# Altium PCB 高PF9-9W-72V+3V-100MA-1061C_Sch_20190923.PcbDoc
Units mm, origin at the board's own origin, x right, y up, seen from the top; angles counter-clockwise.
Board outline 296.5 x 139.5 mm, 2 copper layers (Top Layer, Bottom Layer); 45 components, 27 nets, 117 pads, 18 vias.
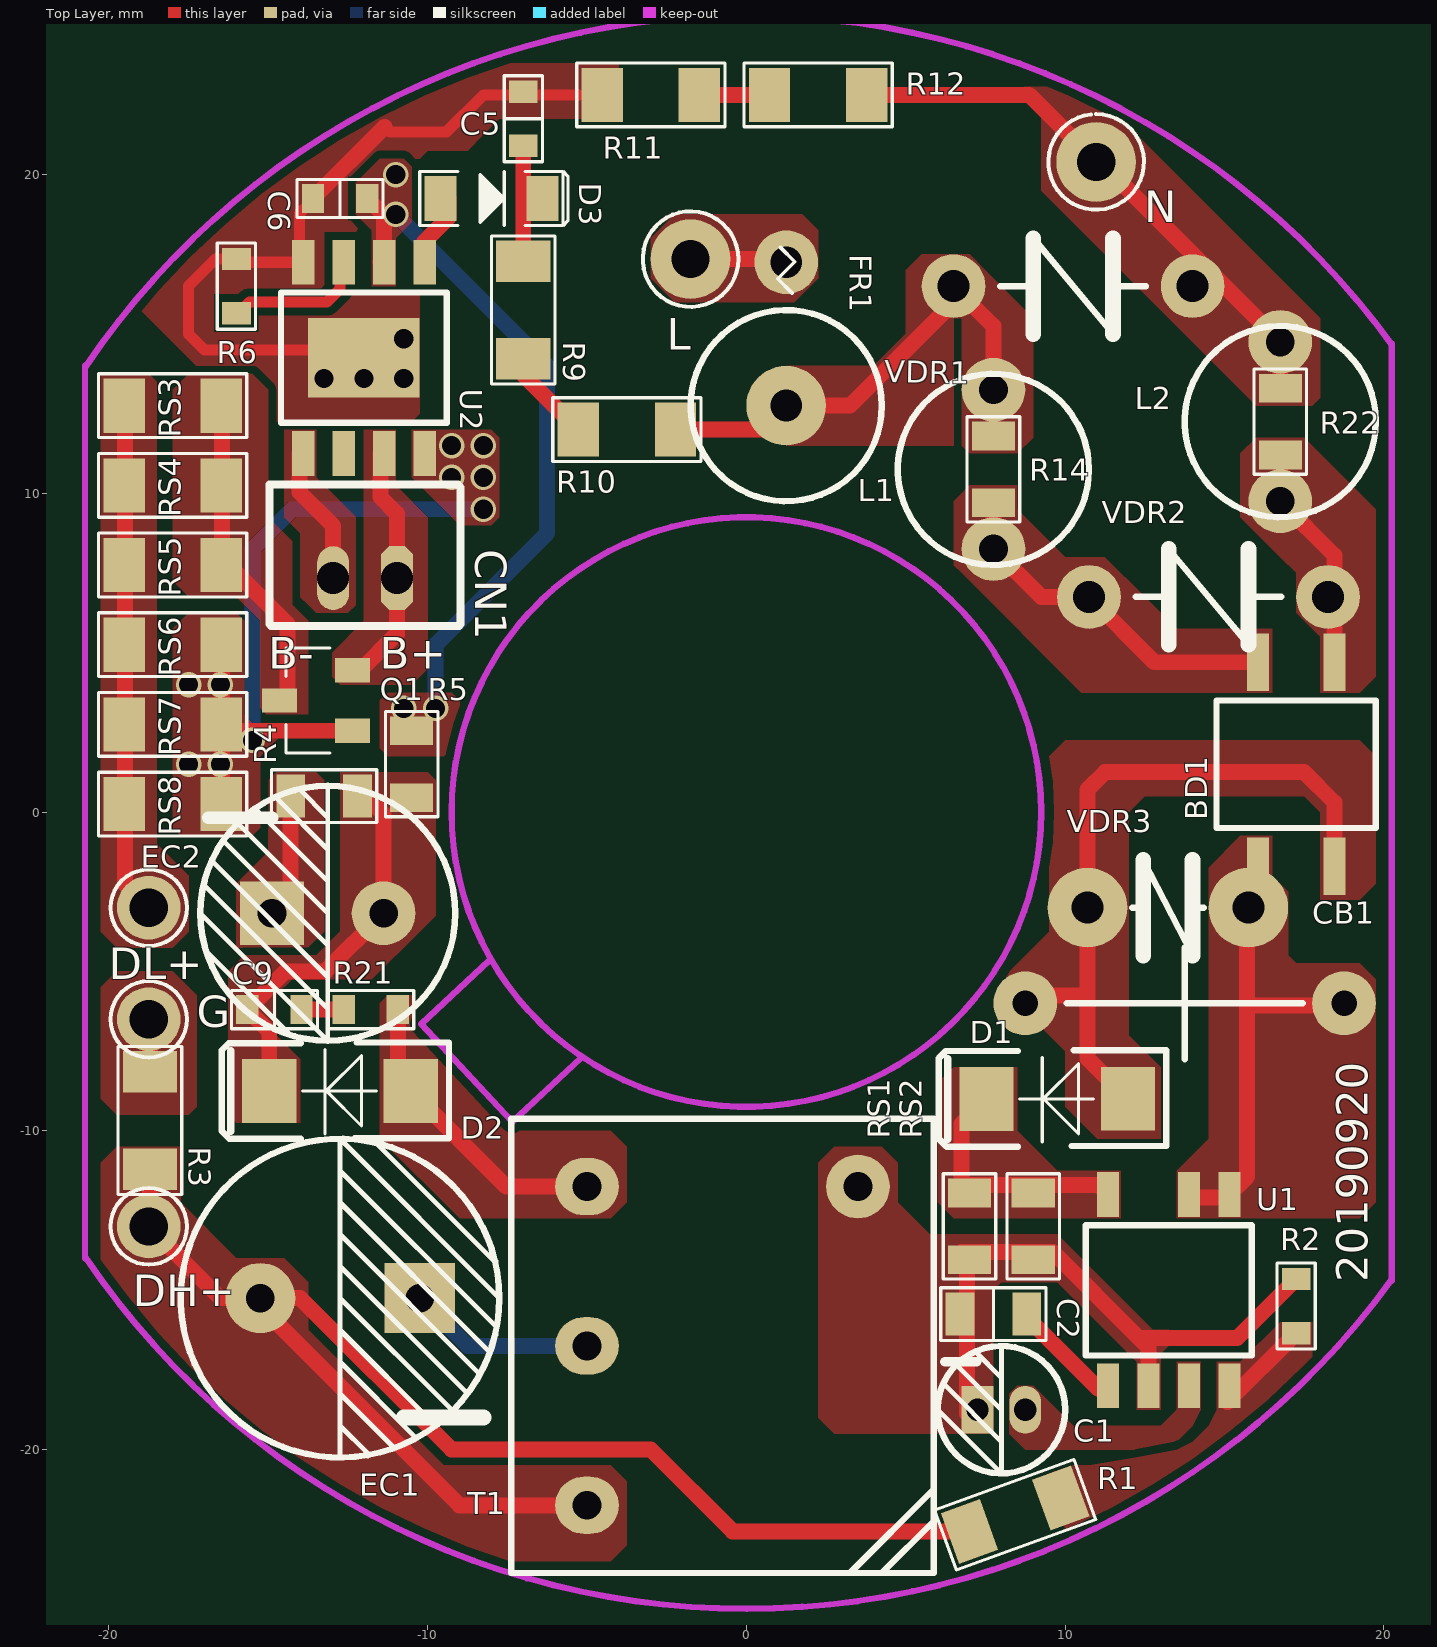
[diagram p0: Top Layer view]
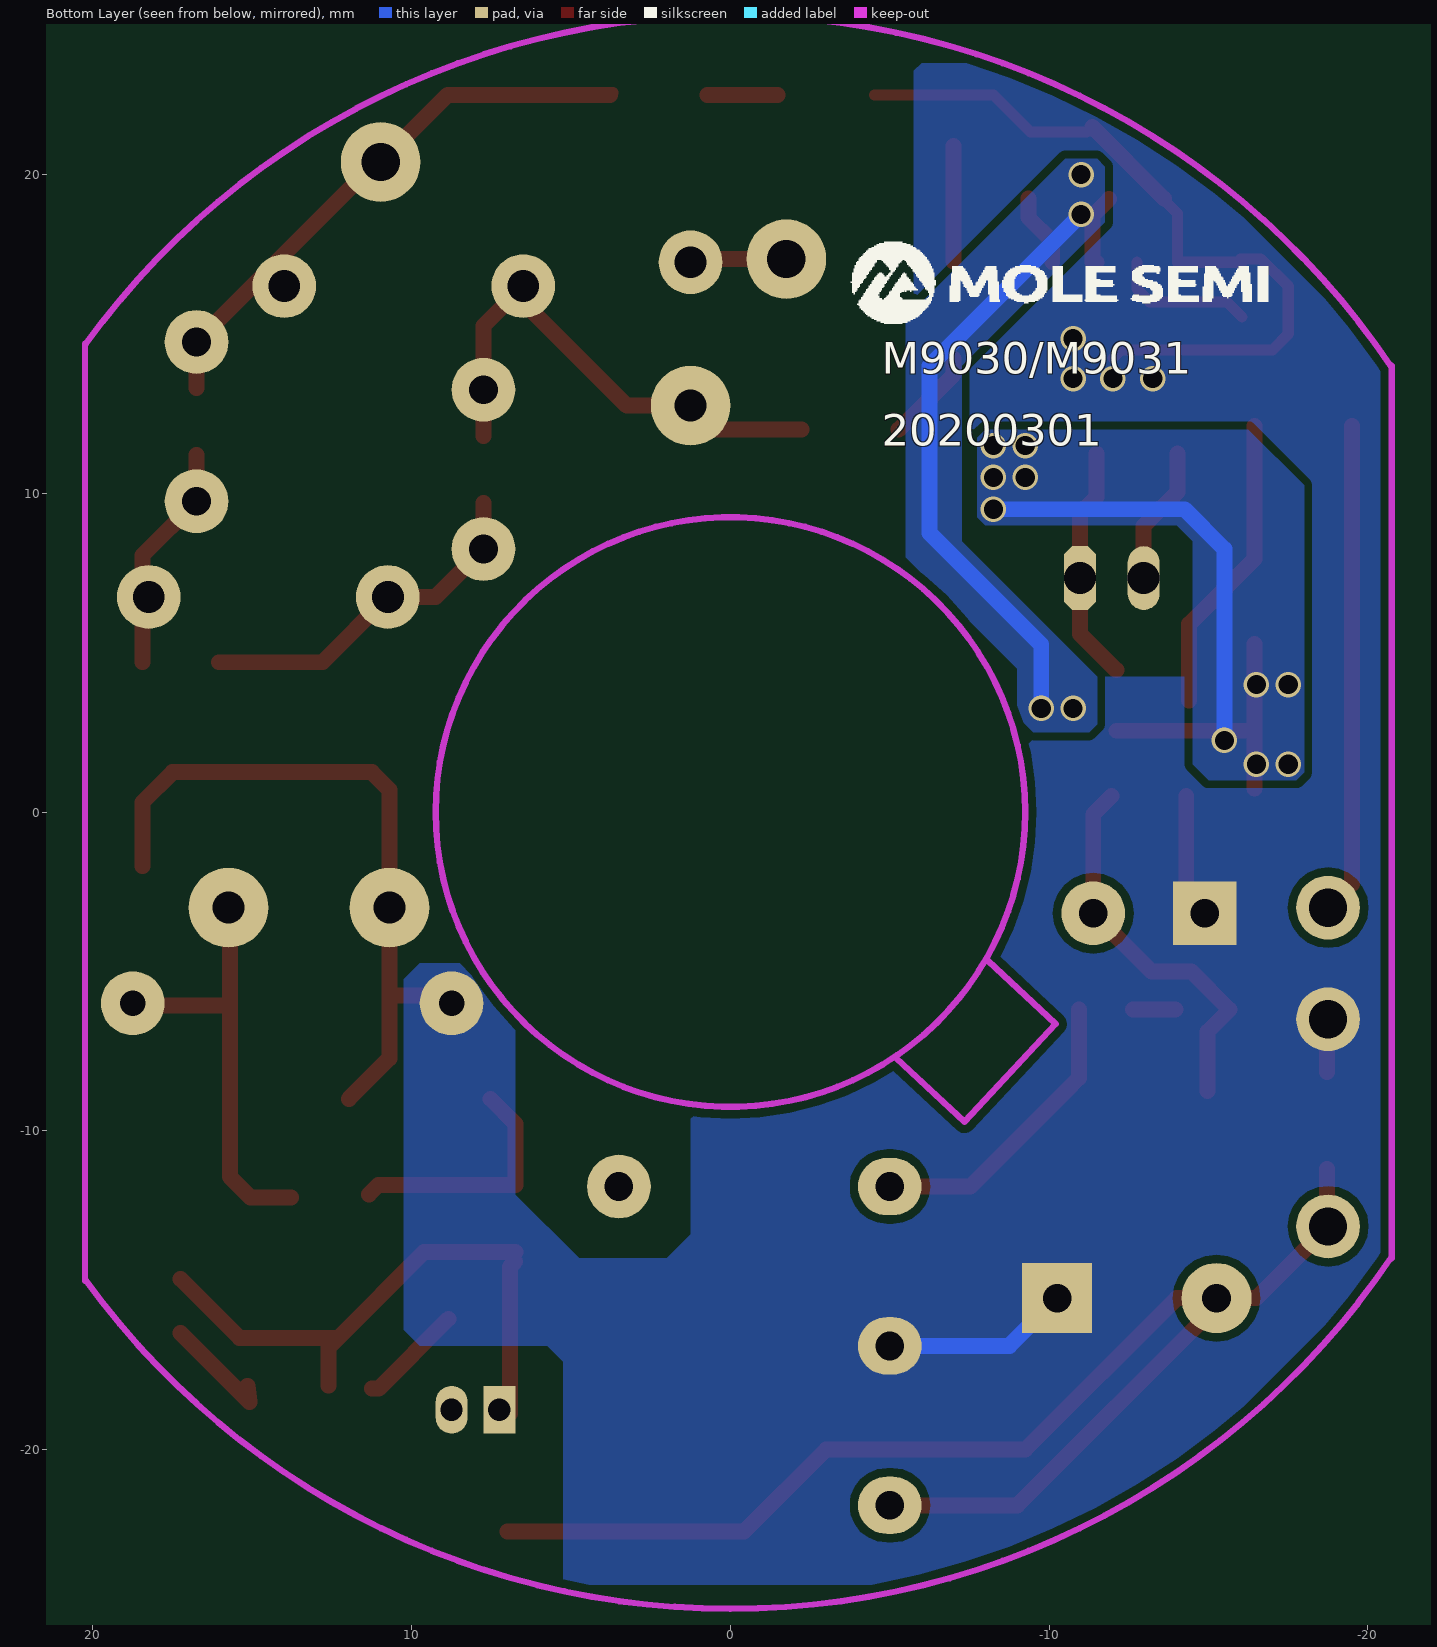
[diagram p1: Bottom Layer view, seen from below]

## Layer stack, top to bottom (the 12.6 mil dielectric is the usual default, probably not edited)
Top Layer: signal copper 0.0356
Dielectric: core 0.32, FR-4, Dk 4.8
Bottom Layer: signal copper 0.0356

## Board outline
-39,-69 -34.7,-69 257.5,-69 257.5,-67.1 257.5,-64.7 257.5,70.2 257.5,70.4 257.5,70.5 256.5,70.5 -39,70.5

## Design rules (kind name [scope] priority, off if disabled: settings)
Clearance [All] p1: gap=0.254
ComponentClearance [All] p1 off: gap=0.254 collisioncheckmode=3 verticalgap=0.254 showdistances=FALSE
FabricationTestPointUsage TestPointUsage [All] p1: valid=0 allowmultiple=FALSE
FabricationTestpoint Testpoint [All] p1: side=3 testpointundercomponent=TRUE minsize=1.016 maxsize=2.54 preferedsize=1.524 minholesize=0 maxholesize=1.016 preferedholesize=0.813 testpointgrid=0.025 allowsidetop=TRUE allowsidebottom=TRUE usegrid=TRUE gridtolerance=0
MinimumSolderMaskSliver [All] p1 off: minsoldermaskwidth=0.254
PlaneConnect [All] p1: planeconnectstyle=Direct reliefexpansion=0.508 reliefentries=4 reliefconductorwidth=0.254 reliefairgap=0.254
PolygonConnect [All] p1: connectstyle=Direct reliefconductorwidth=0.254 reliefentries=4 polygonreliefangle="90 Angle"
RoutingVias [All] p1: holewidth=0.711 width=1.27 viastyle="Through Hole" minholewidth=0.711 minwidth=1.27 maxholewidth=0.711 maxwidth=1.27
SilkToSilkClearance [All] p1 off: silktosilkclearance=0.254
SilkscreenOverComponentPads [IsPad] p1 off: minsilkscreentomaskgap=0.254
SolderMaskExpansion [All] p1 off: expansion=0.102
Width [All] p1: maxlimit=2 minlimit=0.1 preferedwidth=0.4
21 further rules are at their usual default settings.

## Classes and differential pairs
component class "PD65W FAN604+JW7716 20190523": C1 C2 C3 C4 C5 C6 C7 C8 C9 C10 CX1 CY1 CY2 D1 D2 D3 D4 DB1 F1 F2 L1 R1 R2 R3 R4 R5 R6 R7 R10 R11 R12 R26 U1 U2 ZD2 ZV1

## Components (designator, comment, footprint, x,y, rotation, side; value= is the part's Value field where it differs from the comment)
BD1 "BS06" D-BRIDGE-C 17.25,1.5 r0 top
C1 "225" C-1.5/4.0 8,-18.75 r90 top
C2 "105" 2012 7.75,-15.75 r180 top
C5 "104" 1608 -7,21.75 r90 top
C6 "105" 1608 -12.75,19.25 r180 top
C9 "N.A" 1608 -14.808,-6.198 r180 top
CB1 "154J/400V" C-10 13.75,-6 r180 top
CN1 "CN_OUT" PCBComponent_1 -12.014,7.391 r270 top
D1 "ES1J" SMA 9.75,-9 r180 top
D2 "SS24" SMA -12.75,-8.75 r180 top
D3 "6.2V" SOD123 -8,19.25 r0 top (schematic designator ZD1)
EC1 "47uF/100V" C-5.0/10 -12.75,-15.25 r0 top
EC2 "470uF/16V" C-3.5/8.0 -13.132,-3.175 r180 top
FR1 "3.3R/1W" F-D 1.25,16.5 r90 top
L1 "3.3mH/0810" L-5.0/6.0 7.75,10.75 r270 top
L2 "3.3mH/0810" L-5.0/6.0 16.75,12.25 r270 top
Q1 "2301" SOT23 -13.5,3.5 r180 top
R1 "2003" 1206 8.433,-22.047 r20 top
R2 "3301" 0603 17.25,-15.5 r90 top
R3 "1503" 1206 -18.716,-9.677 r90 top
R4 "1001" 0805 -13.25,0.5 r180 top
R5 "0R" 0805 -10.5,1.5 r270 top
R6 "N.A" 0603 -16,16.5 r270 top
R9 "2703" 1206 -7,15.75 r90 top
R10 "2703" 1206 -3.75,12 r180 top
R11 "2703" 1206 -3,22.5 r180 top
R12 "2703" 1206 2.25,22.5 r180 top
R14 "5101" 0805 7.75,10.75 r90 top
R21 "N.A" 0603 -11.786,-6.198 r180 top
R22 "5101" 0805 16.75,12.25 r90 top
RS1 "3R9" 0805 7,-13 r90 top
RS2 "3R6" 0805 9,-13 r90 top
RS3 "2R7" 1206 -18,12.75 r0 top
RS4 "2R7" 1206 -18,10.25 r0 top
RS5 "2R7" 1206 -18,7.75 r0 top
RS6 "2R7" 1206 -18,5.25 r0 top
RS7 "2R7" 1206 -18,2.75 r180 top
RS8 "2R7" 1206 -18,0.25 r180 top
T1 "EE13" EE13 -0.75,-16.75 r180 top
U1 "IC(KP1061C-7P)" SOP8 13.25,-15 r0 top (schematic designator U2)
U2 "IC(M9031-8P)" SOP8N -12,14.25 r180 top
VDR1 "7D561K" R-CR7.5 10.25,16.5 r180 top
VDR2 "7D561K" R-CR7.5 14.5,6.75 r180 top
VDR3 "N.A" R-CR5.0 13.25,-3 r0 top
? "Comment" LOGO(M) -4.25,17 r180 bottom

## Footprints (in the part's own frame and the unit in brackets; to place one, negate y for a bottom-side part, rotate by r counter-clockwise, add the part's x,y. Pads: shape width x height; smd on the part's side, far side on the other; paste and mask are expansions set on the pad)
0603 [mm]
  rect 0.7x0.9 smd: 1(-0.85,0) 2(0.85,0)
  silkscreen extent -1.35,-0.6 1.35,0.6
0805 [mm]
  rect 0.9x1.35 smd: 1(-1.05,0) 2(1.05,0)
  silkscreen extent -1.65,-0.82 1.65,0.82
1206 [mm]
  rect 1.3x1.7 smd: 1(-1.525,0) 2(1.525,0)
  silkscreen extent -2.32,-1 2.33,1
1608 [mm]
  rect 0.7x0.9 smd: 1(-0.85,0) 2(0.85,0)
  silkscreen extent -1.35,-0.6 1.35,0.6
2012 [mm]
  rect 0.9x1.35 smd: 1(-1.05,0) 2(1.05,0)
  silkscreen extent -1.65,-0.82 1.65,0.82
C-1.5/4.0 [mm]
  oval 1.5x1 hole 0.7: 1(0,-0.75)
  rect 1.5x1 hole 0.7: 2(0,0.75)
  silkscreen extent -2,-2 2,2
C-3.5/8.0 [mm]
  round 2 hole 0.9: 1(-1.75,0)
  rect 2x2 hole 0.9: 2(1.75,0)
  silkscreen extent -4,-4 4,4
C-5.0/10 [mm]
  round 2.2 hole 0.9: 1(-2.5,0)
  rect 2.2x2.2 hole 0.9: 2(2.5,0)
  silkscreen extent -5,-5 5,5
C-10 [mm]
  round 2 hole 0.8: 1(-5,0) 2(5,0)
  silkscreen extent -3.7,-1.75 3.7,1.75
D-BRIDGE-C [mm]
  round 0.9 on Top Overlay: 0(-1.75,-1.25)
  rect 0.7x1.8 smd: 1(-1.2,-3.2) 2(-1.2,3.2) 3(1.2,3.2) 4(1.2,-3.2)
  silkscreen extent -2.5,-2 2.5,2
EE13 [mm]
  round 2 hole 0.9: 5(-4.25,-5)
  oval 2x1.8 hole 0.9: 6(4.25,-5) 8(4.25,0) 10(4.25,5)
  silkscreen extent -6.62,-7.12 6.62,7.13
F-D [mm]
  round 2.5 hole 1: 1(-3.75,0)
  round 2 hole 1: 2(0.75,0)
  silkscreen extent -6.75,-3 1.21,3
L-5.0/6.0 [mm]
  round 2 hole 0.9: 1(-2.5,0) 2(2.5,0)
  silkscreen extent -3,-3 3,3
LOGO(M) [mm]
  silkscreen extent -0.47,-1.67 12.62,0.87
PCBComponent_1 [mm]
  oct 2x1 hole 1: 1(0.05,1.05)
  oval 2x1 hole 1: 2(0.05,-0.95)
  silkscreen extent -2.88,-2.95 1.55,3.05
R-CR5.0 [mm]
  round 2.5 hole 1: 1(-2.55,0) 2(2.5,0)
  silkscreen extent -1.15,-1.5 1.1,1.5
R-CR7.5 [mm]
  round 2 hole 1: 1(-3.75,0) 2(3.75,0)
  silkscreen extent -2.29,-1.5 2.29,1.5
SMA [mm]
  rect 1.7x2 smd: 1(-2.22,-0.001) 2(2.22,0.002)
  silkscreen extent -3.42,-1.52 3.71,1.5
SOD123 [mm]
  rect 1x1.4 smd: 1(-1.6,0) 2(1.6,0)
  silkscreen extent -2.25,-0.85 2.4,0.85
SOP8 [mm]
  round 0.9 on Top Overlay: 0(-3,-3) 0(-1.905,-1.29)
  round 0.9 on Mech3: 0(-1.905,-1.29)
  rect 0.7x1.4 smd: 1(-1.905,-3) 2(-0.635,-3) 3(0.635,-3) 4(1.905,-3) 5(1.905,3) 6(0.635,3) 8(-1.905,3)
  silkscreen extent -2.6,-2.05 2.6,2.04
SOP8N [mm]
  round 0.9 on Top Overlay: 0(-3,-3) 0(-1.905,-1.29)
  round 0.9 on Mech3: 0(-1.905,-1.29)
  rect 3.5x2.5 smd: 0(0,0)
  rect 0.7x1.4 smd: 1(-1.905,-3) 2(-0.635,-3) 3(0.635,-3) 4(1.905,-3) 5(1.905,3) 6(0.635,3) 7(-0.635,3) 8(-1.905,3)
  silkscreen extent -2.6,-2.05 2.6,2.04
SOT23 [mm]
  rect 1.1x0.76 smd: 1(-1.143,0.95) 2(1.143,0) 3(-1.143,-0.95)
  silkscreen extent -0.43,-1.65 0.95,1.65

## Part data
BD1: library part D(B-DIODE), "DIODE"
C1 C2 C5 C6 C9: library part C, "CAPACITOR"
CB1: library part C(DIP), "CAPACITOR"
CN1: "CONNECT"
D1 D2: library part D(DIODE), "DIODE"
D3: library part D(ZENER), "DIODE"
EC1 EC2: library part C(+), "CAPACTOR"
FR1: library part FUSE1, "Fuse"
L1 L2: library part L(IND), "INDUCTOR"
Q1: library part Q(MOSFET-N), "MOSFET"
R1 R2 R3 R4 R5 R6 R9 R10 R11 R12 R14 R21 R22 RS1 RS2 RS3 RS4 RS5 RS6 RS7 RS8: library part R, "RESISTOR"
T1: library part Trans, "Transformer"
U1: library part IC(JW1768-8P), "IC"
U2: "IC"
VDR1 VDR2 VDR3: library part D(VARISTOR), "DIODE"

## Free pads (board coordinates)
  round 2 hole 1.2: 1(-18.75,-13) 1(-18.75,-6.5) 1(-18.75,-3)
  round 2.5 hole 1.2: 1(-1.753,17.348) 1(10.973,20.396)

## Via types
v1: diameter 0.8, hole 0.6, Top Layer to Bottom Layer, 18 vias

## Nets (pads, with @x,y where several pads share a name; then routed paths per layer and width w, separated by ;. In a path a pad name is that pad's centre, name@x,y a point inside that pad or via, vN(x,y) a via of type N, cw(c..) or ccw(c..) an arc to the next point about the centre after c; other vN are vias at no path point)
3V/LED2+: Q1.1 RS6.2 RS7.1 RS8.1 U2.8 | length 22.7
  Top Layer w0.5: RS8.1@-16.446,0.731 RS7.1@-16.446,2.5 ; RS6.2@-16.446,5.277 RS7.1@-16.446,2.5 ; Q1.1@-12.107,2.55 Q1.1 -16.396,2.55 RS7.1@-16.446,2.5
  Bottom Layer w0.5: v1(-15.5,2.25) -15.5,8.25 -14.25,9.5 v1(-8.25,9.5)
  other v1: -17.5,1.5 -16.5,1.5 -17.5,4 -16.5,4 -9.25,10.5 -8.25,10.5 -9.25,11.5 -8.25,11.5
72V/LED1+: EC1.1 pad.1@-18.75,-13 R1.1 R3.1 T1.10 | length 44.4
  Top Layer w0.5: R3.1 -18.716,-12.966 -18.75,-13 -16.5,-15.25 EC1.1 -15.25,-15.5 -9,-21.75 T1.10 ; EC1.1@-15,-15.25 -14,-15.25 -9.25,-20 -3,-20 -0.431,-22.569 R1.1
ACL: D3.1 U2.1 | length 2.3
  Top Layer w0.5: U2.1 -10.095,17.905 -9.35,18.65 D3.1@-9.35,19.25
AGND: C1.2 C2.2 R2.2 RS1.1 RS2.1 T1.5 U1.2 | length 18.8
  Top Layer w0.5: RS1.1@6.75,-13.8 9.609,-13.8 12.309,-16.5 ; RS1.1@6.756,-14.106 6.921,-14.27 C1.2@6.921,-18.872 ; U1.2 12.615,-16.806 12.309,-16.5 ; R2.2 15.4,-16.5 12.309,-16.5
GND: BD1.4 C5.2 C6.2 CB1.2 D1.1 EC1.2 EC2.2 pad.1@-18.75,-6.5 R3.2 R4.2 R6.1 R11.2 T1.8 U2.0@-12,14.25 U2.4 VDR3.1 | length 57.4
  Top Layer w0.35: R6.1@-16.053,17.233 -16.036,17.249 -14.021,17.249 -14.021,18.782 C6.2@-13.577,19.227 ; R6.1 -16.65,17.35 -17.5,16.5 -17.5,15 -17,14.5 -12.25,14.5 U2.0@-12,14.25 ; -11.184,21.334 -9.416,21.334 -8.25,22.5 R11.2
  Top Layer w0.5: pad.1@-18.75,-6.5 -18.716,-6.534 R3.2 ; EC2.2 -14.3,-2.593 R4.2 ; C6.2 -11.35,21.5 ; CB1.2@9,-5.75 10.7,-5.75 ; D1.1 10.7,-7.728 10.7,-5.75 ; BD1.4 18.45,0.3 17.5,1.25 11.25,1.25 10.7,0.7 VDR3.1 10.7,-5.75
  Bottom Layer w0.5: EC1.2 -8.75,-16.75 T1.8
  other v1: -13.25,13.6 -12,13.6 -10.75,13.6 -10.75,14.85
NetBAT_1: CN1.1 Q1.3 U2.7 | length 7.5
  Top Layer w0.5: Q1.3@-12.107,4.45 -10.964,5.593 CN1.1 -10.964,9.364 -11.481,9.881 U2.7@-11.481,11.249
NetBAT_2: CN1.2 U2.5 | length 4.3
  Top Layer w0.5: U2.5@-14.021,11.249 -14.021,10.033 -12.964,8.976 CN1.2
NetBD1_1: BD1.1 CB1.1 U1.5 U1.6 VDR3.2 | length 13.8
  Top Layer w0.5: U1.6@13.792,-12.088 15.062,-12.088 15.708,-11.442 15.708,-6.02 ; VDR3.2@15.708,-3.277 15.708,-6.02 ; CB1.1@19.173,-6.071 15.759,-6.071 15.708,-6.02
NetBD1_2: BD1.2 L1.2 R14.1 VDR2.2 | length 11.2
  Top Layer w0.5: R14.1 L1.2 9.25,6.75 VDR2.2 12.8,4.7 BD1.2
NetBD1_3: BD1.3 L2.2 R22.1 VDR2.1 | length 7.2
  Top Layer w0.5: R22.1 L2.2 18.45,8.05 BD1.3
NetC1_1: C1.1 U1.3
NetC2_1: C2.1 U1.1 | length 3.3
  Top Layer w0.5: C2.1@8.848,-15.9 11.035,-18.088 U1.1@11.252,-18.088
NetC5_1: C5.1 D3.2 R9.2 | length 3.6
  Top Layer w0.5: R9.2 C5.1
NetC6_1: C6.1 R5.1 U2.2 | length 21.1
  Top Layer w0.5: C6.1@-11.875,19.228 -11.365,18.717 U2.2
  Bottom Layer w0.5: v1(-11,18.75) -6.25,14 -6.25,8.75 -9.75,5.25 v1(-9.75,3.25)
  other v1: -10.75,3.25 -11,20
NetC9_1: C9.1 R21.2 | length 1.3
  Top Layer w0.5: C9.1 R21.2
NetD1_2: D1.2 RS1.2 RS2.2 U1.8 | length 7.7
  Top Layer w0.5: D1.2 6.75,-9.781 6.75,-11.7 9,-11.7 11.045,-11.7 U1.8
NetD2_1: D2.1 R21.1 T1.6 | length 9.5
  Top Layer w0.5: R21.1 -10.936,-8.343 D2.1 -7.528,-11.75 T1.6
NetFR1_1: FR1.2 pad.1@-1.753,17.348 | length 3
  Top Layer w0.5: pad.1@-1.753,17.348 1.152,17.348 FR1.2
NetFR1_2: FR1.1 L1.1 R10.1 R14.2 VDR1.2 | length 16.1
  Top Layer w0.5: R10.1 0.5,12 FR1.1 3.25,12.75 6.5,16 VDR1.2 7.75,15.25 L1.1 R14.2
NetL2_1: L2.1 pad.1@10.973,20.396 R12.1 R22.2 VDR1.1 | length 17.7
  Top Layer w0.35: R12.1@3.684,22.568 R12.1@3.775,22.568
  Top Layer w0.5: R12.1 8.869,22.5 10.973,20.396 11.104,20.396 L2.1 R22.2
NetLED2n_1: pad.1@-18.75,-3 RS3.1 RS4.1 RS5.1 RS6.1 RS7.2 RS8.2 | length 15.4
  Top Layer w0.5: RS3.1@-19.496,12.11 -19.496,-2.254 pad.1@-18.75,-3
NetQ1_2: Q1.2 RS3.2 RS4.2 RS5.2 | length 9.5
  Top Layer w0.5: RS3.2@-16.446,12.11 -16.446,7.946 -14.393,5.893 Q1.2@-14.393,3.5
NetR1_2: R1.2 R2.1 U1.4 | length 3.6
  Top Layer w0.5: U1.4 15.095,-18.505 R2.1
NetR6_2: R6.2 U2.3 | length 4.5
  Top Layer w0.35: R6.2@-16.053,15.533 -15.584,16.002 -13.157,16.002 -12.751,16.408 U2.3@-12.751,17.249
NetR9_1: R9.1 R10.2 | length 2.9
  Top Layer w0.5: R9.1 -7,13.725 R10.2
NetR11_1: R11.1 R12.2 | length 2.2
  Top Layer w0.5: R11.1 R12.2
VDD/5V: C9.2 D2.2 EC2.1 R4.1 R5.2 | length 12.3
  Top Layer w0.5: D2.2 -14.97,-6.885 C9.2 -14.461,-5 -13.207,-5 EC2.1 -11.382,-0.068 R4.1@-11.95,0.5
pads on no net: BD1.0 U1.0 U2.0@-9,17.25 U2.0@-10.095,15.54 U2.6

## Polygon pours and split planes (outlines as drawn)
GND on Top Layer "ds" (solid, remove dead copper, pour order 1000): -8.5,23.5 -4,23.5 -4,21.75 -5.75,21.75 -7.75,21.75 -8.25,21.25 -8.75,20.75 -9.5,20.75 -10,20.75 -10.25,20.5 -10.25,13 -10.25,12.5 -10.5,12.25 -14.5,12.25 -15.5,12.25 -19.5,16.25 -15.25,20.5 -14.75,20.5
NetL2_1 on Top Layer "Top Layer-No Net 1" (solid, remove dead copper, pour order 0): 9.25,19.5 16,12.75 16.75,12.75 17.75,12.75 18,13 18,15.5 11.25,22.25 10.75,22.5 10.25,22.75 8.5,22.75 9.25,22.25 9.25,21.75 9.25,20.5 9.25,20
NetBD1_3 on Top Layer "Top Layer-No Net 1" (solid, remove dead copper, pour order 2): 18,3.75 19.25,3.75 19.75,4.25 19.75,9.5 17.5,11.75 16,11.75 15.5,11.25 15.5,10 15.5,9.25 16.75,8 17.25,7.5 17.25,6.75 17.25,6.25 18,5.5 18,3.75
NetBD1_2 on Top Layer "Top Layer-No Net 1" (solid, remove dead copper, pour order 4): 16.5,5.75 16.5,3.75 15.75,3.75 11.5,3.75 10.5,3.75 6.75,7.5 6.5,7.75 6.5,9.75 7,10.25 8.5,10.25 8.5,9.5 10,8 11,8 11.25,8 12.5,6.75 13.5,5.75 16.5,5.75
GND on Top Layer "Top Layer-No Net 1" (solid, remove dead copper, pour order 6): 18,-2.75 19,-2.75 19.25,-2.75 19.75,-2.25 19.75,-1.5 19.75,1.75 19.25,2.25 18,2.25 10,2.25 9.5,1.75 9.5,0 9.5,-4.5 12,-4.5 12,-3.25 12,-0.75 12,0 12.5,0.5 13.25,0.5 17.5,0.5 18,0 18,-2.75
NetBD1_1 on Top Layer "Top Layer-No Net 1" (solid, remove dead copper, pour order 8): 14.5,-1.75 14.5,-4.25 14.5,-10.25 13.5,-11.25 13.5,-12.75 15,-12.75 18.25,-12.75 19.25,-12.75 19.75,-12.25 19.75,-10.75 19.75,-5.25 19.25,-4.75 18.75,-4.75 17.25,-4.75 17,-4.5 17,-2.75 17,-2.5 16.5,-2 16.5,-0.75 15.5,-0.75 14.5,-1.75 14.5,-2.25
GND on Top Layer "Top Layer-No Net 1" (solid, remove dead copper, pour order 10): 12,-4.5 12,-6.75 12,-7 13,-8 13,-9.5 13,-10.25 11,-10.25 10.5,-9.75 10,-9.25 10,-8.25 10,-7.5 9.25,-6.75 8.75,-6.75 8.5,-6.75 8,-6.25 8,-5.25 9.5,-3.75 9.75,-3.5 12,-3.5 12,-4.5
NetD1_2 on Top Layer "Top Layer-No Net 1" (solid, remove dead copper, pour order 12): 6.75,-8 8.5,-8 8.5,-10 9.5,-11 9.75,-11.25 11.75,-11.25 11.75,-12.75 10.75,-12.75 6.5,-12.75 6,-12.25 6,-10.75 6,-8.5 6.5,-8 6.75,-8
AGND on Top Layer "Top Layer-No Net 1" (solid, remove dead copper, pour order 14): 4.75,-11 4.75,-12 4.75,-12.25 5.75,-13.25 9,-13.25 9.75,-13.25 10.25,-13.75 12.75,-16.25 13.25,-16.25 13.25,-16.75 13,-17 13,-17.25 13,-18.75 12.25,-18.75 12.25,-17.25 9.75,-14.75 8.5,-14.75 8,-14.75 7.75,-15 7.75,-19.5 6.5,-19.5 6,-19.5 5.75,-19.5 3.25,-19.5 2.75,-19.5 2.25,-19 2.25,-14.75 2.25,-11 2.75,-10.5 4.25,-10.5 4.75,-11
72V/LED1+ on Top Layer "Top Layer-No Net 1" (solid, remove dead copper, pour order 16): -3.75,-21.25 -3.75,-22.25 -3.75,-23 -4.25,-23.5 -5,-23.5 -12.25,-23.5 -18.75,-17 -20.25,-15.5 -20.25,-12.75 -20.25,-11 -19.75,-10.5 -17.75,-10.5 -17.75,-12.25 -16,-14 -14.75,-14 -14.5,-14 -14,-14.5 -13.75,-14.75 -13.75,-16.25 -9.5,-20.5 -8,-20.5 -4.25,-20.5 -3.75,-21 -3.75,-21.5
NetD2_1 on Top Layer "Top Layer-No Net 1" (solid, remove dead copper, pour order 18): -11.5,-6 -11.5,-9 -11.5,-10.25 -9,-12.75 -5.5,-12.75 -4.25,-12.75 -3.75,-12.25 -3.75,-11.5 -3.75,-10.5 -4.25,-10 -5.75,-10 -7.25,-10 -9.5,-7.75 -10.5,-6.75 -10.5,-6.25 -10.5,-5.75 -11.25,-5.75 -11.5,-6
VDD/5V on Top Layer "Top Layer-No Net 1" (solid, remove dead copper, pour order 20): -14,-9.75 -14,-7.75 -14.75,-7 -14.75,-6.5 -14.75,-5.75 -14.25,-5.25 -13.25,-5.25 -11.75,-5.25 -10.25,-3.75 -10.25,-1.75 -12.5,-1.75 -12.5,-3.25 -12.5,-3.5 -13.5,-4.5 -13.75,-4.5 -15.75,-4.5 -16.25,-5 -16.25,-6.5 -16.25,-9.5 -16,-9.75
NetLED2n_1 on Top Layer "Top Layer-No Net 1" (solid, remove dead copper, pour order 22): -17.5,-3.5 -17.5,-2.25 -17.5,-2 -18.5,-1 -18.5,0.25 -18.5,13.5 -18.75,13.75 -20.25,13.75 -20.25,-3.75 -19.75,-4.25 -18.25,-4.25 -18,-4.25 -17.5,-3.75 -17.5,-3.25
3V/LED2+ on Top Layer "Top Layer-No Net 1" (solid, remove dead copper, pour order 24): -15.75,6 -15.75,4.5 -15.75,3.05 -15.25,2.55 -14.5,2.55 -14.5,2.5 -15,2 -15.25,1.75 -15.25,-0.5 -15.5,-0.75 -17.25,-0.75 -17.75,-0.75 -18,-0.5 -18,1 -18,5.75 -17.5,6.25 -16,6.25
NetQ1_2 on Top Layer "Top Layer-No Net 1" (solid, remove dead copper, pour order 26): -18,13.25 -18,7.25 -17.5,6.75 -16.25,6.75 -16,6.75 -15.75,6.5 -15.25,6 -15.25,4.25 -15.25,3.25 -15,3 -13.75,3 -13.75,3.75 -13.75,5.75 -13.75,6 -14,6.25 -14.25,6.5 -14.25,8.5 -15,9.25 -15,9.75 -15,13.25 -15.5,13.75 -17.5,13.75
NetBAT_1 on Top Layer "Top Layer-No Net 1" (solid, remove dead copper, pour order 28): -11,12 -11,10.5 -11,10.25 -10.25,9.5 -10,9.25 -10,6.75 -10,4.5 -10.5,4 -11.75,4 -12.75,4 -13,4.25 -13,5 -12,6 -12,7.25 -12,12 -11,12
NetBAT_2 on Top Layer "Top Layer-No Net 1" (solid, remove dead copper, pour order 30): -13.5,12 -13.5,10.5 -13,10 -12.25,9.25 -12.25,8 -12.25,6.5 -12.5,6.25 -13,6.25 -13.5,6.25 -13.75,6.5 -14,6.75 -14,7 -14,8.75 -14.25,9 -14.5,9.25 -14.5,10.75 -14.5,12 -13.5,12
NetFR1_2 on Top Layer "Top Layer-No Net 1" (solid, remove dead copper, pour order 32): 8.5,11.25 9,11.75 9,13 9,15.5 7.5,17 7,17.5 6.25,17.5 6,17.5 5.5,17.5 5,17 5,15 4,14 1.25,14 1.25,11.5 6.5,11.5 6.5,13.75 6.5,15.5 6.75,15.5 6.75,11.5 7,11.25
NetFR1_1 on Top Layer "Top Layer-No Net 1" (solid, remove dead copper, pour order 34): 2.25,17.25 2.25,16.75 1.75,16.25 1.5,16 -1.75,16 -2.25,16 -3,16.75 -3,18 -2.25,18.75 1.5,18.75 1.75,18.75 2.25,18.25 2.25,17.25
3V/LED2+ on Top Layer "Top Layer-No Net 1" (solid, remove dead copper, pour order 36): -10.25,12 -9,12 -8.25,12 -8,12 -7.75,11.75 -7.75,10.75 -7.75,9.25 -8,9 -9,9 -10.5,10.5 -10.5,12
VDD/5V on Top Layer "Top Layer-No Net 1" (solid, remove dead copper, pour order 38): -12.75,1.25 -12.75,-4.25 -10.75,-4.25 -9.75,-3.25 -9.75,1 -10,1.25 -10.25,1.25 -12.75,1.25
NetC6_1 on Top Layer "Top Layer-No Net 1" (solid, remove dead copper, pour order 40): -11.25,1.75 -9.5,1.75 -9.25,2 -9,2.25 -9,3.25 -9,3.5 -9.25,3.75 -10.75,3.75 -11.25,3.75 -11.5,3.5 -11.5,2 -11.25,1.75
NetC6_1 on Top Layer "Top Layer-No Net 1" (solid, remove dead copper, pour order 46): -12.25,19.75 -11.75,20.25 -11.5,20.5 -11,20.5 -10.75,20.5 -10.5,20.25 -10.5,19.5 -10.5,18.5 -11,18 -11,16.5 -11.75,16.5 -11.75,17.5 -11.75,18.25 -12.25,18.75 -12.25,19.75
GND on Top Layer "Top Layer-No Net 1" (solid, remove dead copper, pour order 54): -17.25,-6.5 -17.25,-8.5 -17.25,-9.25 -17.5,-9.5 -19,-9.5 -19.75,-9.5 -20.25,-9 -20.25,-5.75 -20.25,-5.5 -19.75,-5 -18,-5 -17.25,-5.75 -17.25,-6
NetR1_2 on Top Layer "Top Layer-No Net 1" (solid, remove dead copper, pour order 56): 14.75,-17.5 14.75,-18.75 14.5,-19.25 14,-19.75 13.5,-20 12.25,-20.25 10.75,-20.5 10.25,-20.5 9.5,-20.75 10,-22.5 13.5,-21.5 15.5,-20 15.5,-18.5 15.5,-17.5 15.5,-17.25 14.75,-17.25 14.75,-17.5
NetC1_1 on Top Layer "Top Layer-No Net 1" (solid, remove dead copper, pour order 58): 14.25,-17.25 14.25,-18.75 14,-19.25 13.75,-19.5 13.5,-19.75 13,-20 12.25,-20 8.75,-20 8.25,-19.5 8.25,-18.5 8.25,-18.25 8.5,-18 9,-18 9.25,-18.25 10,-19 10.25,-19.25 13,-19.25 13.5,-18.75 13.5,-17.25
NetR1_2 on Top Layer "Top Layer-No Net 1" (solid, remove dead copper, pour order 60): 15,-17.25 15.5,-17.25 16.75,-16 17.75,-16 17.75,-18 16,-19.5 15.25,-19.75 15.25,-17.25
GND on Top Layer "Top Layer-No Net 1" (solid, remove dead copper, pour order 62): -16,-4.25 -14,-4.25 -13.75,-4.25 -13.25,-3.75 -13.25,0.5 -13.25,1 -13.5,1.25 -14.75,1.25 -15,1 -15,-0.5 -15,-1.25 -16,-2.25 -16,-4.25
3V/LED2+ on Bottom Layer "Top Layer-No Net 1" (solid, remove dead copper, pour order 42): -8,9 -12,9 -13.5,9 -14,9 -14.5,8.5 -14.5,4.75 -14.5,1.5 -15,1 -15.5,1 -17.75,1 -18,1.25 -18,2.75 -18,10.25 -16.25,12 -14.25,12 -8,12 -7.75,11.75 -7.75,9.25
NetC6_1 on Bottom Layer "Top Layer-No Net 1" (solid, remove dead copper, pour order 44): -11.25,2.5 -9.5,2.5 -9,3 -9,3.75 -9,4.5 -7.25,6.25 -5.5,8 -5.5,9.5 -5.5,15 -5.5,15.5 -10.5,20.5 -11.5,20.5 -11.75,20.25 -11.75,18.75 -11.75,18.5 -7.25,14 -7.25,13.75 -7.25,10.5 -7.25,8.5 -8.75,7 -11.5,4.25 -11.5,3.5 -11.5,2.75
GND on Bottom Layer "Top Layer-No Net 1" (solid, remove dead copper, pour order 48): -5.75,23.25 -5.75,14 -5.75,9.25 -6,9 -9.5,9 -14.75,9 -14.75,4.25 -9.25,4.25 -9,4.5 -8,4.5 -8,-3.75 -3.5,-8.25 -3.25,-8.5 -3.25,-17 -3.25,-23.75 -3.75,-24.25 -4.75,-24.25 -10.5,-24.25 -20.75,-14 -20.75,13 -20.75,14 -12.5,22.25 -11.25,23.5 -7.25,23.5 -6,23.5 -5.75,23.25
GND on Bottom Layer "Top Layer-No Net 1" (solid, remove dead copper, pour order 50): 9,-4.75 9.75,-4.75 10.25,-5.25 10.25,-5.75 10.25,-16.25 9.75,-16.75 7.75,-16.75 5.75,-16.75 5.25,-17.25 5.25,-24.241 -3.741,-24.241 -3.75,-24.232 -3.75,-19.75 -3.75,-8.954 -3.679,-8.883 -3.546,-8.75 1.25,-8.75 1.25,-13.25 2,-14 4.25,-14 4.75,-14 6.75,-12 6.75,-8 6.75,-6.5 8.5,-4.75

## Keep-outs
Keep-Out Layer:
  circle w0.2: c0,0 r9.25
  lines w0.2: -20.75,-14 -20.75,14 ; -20.724,-13.983 ccw(c0,0) 20.231,-14.686 ; -20.724,13.982 cw(c0,0) 20.231,14.687 ; -8.07,-4.654 -10.208,-6.648 -7.344,-9.72 -5.187,-7.708 ; 20.25,-14.7 20.25,14.7

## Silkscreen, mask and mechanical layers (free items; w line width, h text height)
Top Overlay:
  circle w0.127: c-1.753,17.348 r1.5
  circle w0.127: c-18.75,-13 r1.2
  circle w0.127: c-18.75,-6.5 r1.2
  circle w0.127: c-18.75,-3 r1.2
  lines w0.127: 10.81,21.887 ccw(c10.973,20.396) 10.973,21.896
  text "N" at 13.5,19.5 h1 r180
  text "L" at -2.5,14.5 h1
  text "DL+" at -20,-5.25 h1
  text "G" at -17.25,-6.75 h1
  text "20190920" at 19.5,-14.75 h1 r90
  text "DH+" at -19.25,-15.5 h1
Bottom Overlay:
  text "M9030/M9031" at -4.75,13.75 h1
  text "20200301" at -4.75,11.5 h1
Mechanical 1:
  lines w0.254: -20.75,-28.5 -20.75,-26.5 ; -19.226,-28.008 -20.75,-27.5 ; -19.226,-26.992 -20.75,-27.5 ; -5.227,-27.5 -20.75,-27.5 ; 4.727,-27.5 20.25,-27.5 ; 18.726,-28.008 20.25,-27.5 ; 18.726,-26.992 20.25,-27.5 ; 20.25,-28.5 20.25,-26.5 ; 22.5,-25 24.5,-25 ; 22.5,25 24.5,25 ; 22.992,-23.476 23.5,-25 ; 22.992,23.476 23.5,25 ; 23.5,-5.104 23.5,-25 ; 23.5,5.104 23.5,25 ; 24.008,-23.476 23.5,-25 ; 24.008,23.476 23.5,25
  text ".Printout_Name" at -21.75,28.25 h0.7
  text "50 (mm)" at 24.414,-4.85 h1.52 r90
  text "41 (mm)" at -4.973,-28.414 h1.52
Drill Drawing:
  text ".Legend" at -21.75,29.5 h0.7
